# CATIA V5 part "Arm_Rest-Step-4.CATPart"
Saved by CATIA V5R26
Part number: Arm_Rest
Bounding box of the stored display mesh (mm): x 743.798 to 1432.298, y -782.976 to 0, z 330.43 to 551.996
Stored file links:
  D:\LinkedIn Learning\NURBS\CATIA\Class Parts\Arm_Rest-Step-5.CATPart
  D:\LinkedIn Learning\NURBS\Arm_Rest.CATPart
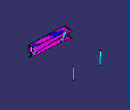
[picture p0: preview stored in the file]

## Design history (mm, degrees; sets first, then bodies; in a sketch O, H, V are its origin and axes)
AxisSystem1: origin (0, 0, 0), X (1, 0, 0), Y (0, 1, 0), Z (0, 0, 1)
StDynAnalysisRootNodeFeature1 "CATStDynAnalysisRootNodeName"
Set1 "REF DATA"
  CLDGeom1 "TOP"
  CLDGeom2 "FRONT"
  CLDGeom3 "AFT_BLEND"
  CLDGeom4 "END_AFT"
  CLDGeom5 "FORWARD_BLEND"
  CLDGeom6 "BOTTOM"
  CLDGeom7 "END_FORWARD"
  CLDGeom8 "UPPER_BLENDS"
  CLDGeom9 "LOWER_BLENDS"
  DatumSurface1 "DOOR_TRIM_SURFACE"
Set2 "FORM"
  Set3 "SLABS"
    DatumSurface2 to DatumSurface6
  Set4 "CURVES"
    St3DCurveFeature1 "CATSt3DCurveFeatureName": Order 6, CreationType 1, ClosureMode false, ConstructionPoints ({point type Coord, X 863.1168, Y 0, Z 551.1449}; {point type Coord, X 868.9503, Y 0, Z 330.43}), SymmetryMode false
    St3DCurveFeature2 "CATSt3DCurveFeatureName": Order 6, CreationType 1, ClosureMode false, ConstructionPoints ({point type Coord, X 1369.3867, Y 0, Z 551.9965}; {point type Coord, X 1358.4038, Y 0, Z 335.6826}), SymmetryMode false
    Intersect1: ToIntersect1 DatumSurface4, ToIntersect2 DatumSurface5
    Intersect2: ToIntersect1 DatumSurface6, ToIntersect2 DatumSurface4
    CurvePar1: Offset Intersect2, Support DatumSurface6, Offset2 0, Offset1 30
    CurvePar2: Offset Intersect1, Support DatumSurface5, Offset2 50, Offset1 20
    Project1: ToProject St3DCurveFeature1, Support DatumSurface4, Direction edge [YZ plane of AxisSystem1 | XY plane of AxisSystem1]
    Project2: ToProject St3DCurveFeature2, Support DatumSurface4, Direction edge [YZ plane of AxisSystem1 | XY plane of AxisSystem1]
Body1 (main body)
